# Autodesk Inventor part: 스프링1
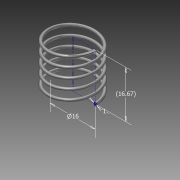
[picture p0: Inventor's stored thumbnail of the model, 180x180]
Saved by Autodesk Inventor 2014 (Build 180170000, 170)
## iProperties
Created: 2015-11
Part Number: 스프링1
Material: 강철, 탄소
Document SubType Name: Modeling
Designer: SEC
Mass: 1.5393 g
Surface Area: 7.90158 cm^2
Volume: 0.195591 cm^3
Density: 7.87 g/cm^3
Appearance: 반연마
Author: SEC
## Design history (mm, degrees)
sketch "스케치1"
  geometry: L1 (0, 0)-(8, 0); L2 (8, 0)-(8, 16.67); L3 (8, 16.67)-(0, 16.67); L4 (0, 16.67)-(0, 0); C1 r 0.5 at (8, 0)
  constraints: 8 end point, 2 parallel, 1 centre point, 1 coincident, 1 horizontal, 1 perpendicular
  dimensions: "d1" = 16 diameter of L2 L4; "d2" = 16.66987 distance of L1.end L2.end (derived); "d3" = 1 diameter of C1
feature "코일1" pitch "d4" = 10; turns "d6" = 5; dims "d5" = 16.66987 (= d2), "d7" = 0, angle "d8" = 90 deg, angle "d9" = 90 deg, "d10" = 0, "d11" = 0
sketch "스케치2"
  geometry: L1 (-8.5, 0)-(-7.5, 0) reference; 1 further point
  constraints: 1 horizontal alignment
extrude "돌출1" cut sketch "스케치2" stored distance "d12" = 10; taper "d13" = 0 deg
node "작업 평면2"
sketch "스케치3"
  geometry: L1 (0.5, 0)-(-0.5, 0) reference; 1 further point
  constraints: 1 horizontal alignment
extrude "돌출2" cut sketch "스케치3" stored distance "d15" = 10; taper "d16" = 0 deg
node "솔리드1"
node "절단 모서리 투영1"
node "절단 모서리 투영2"
other parameters: "d14" = 0
